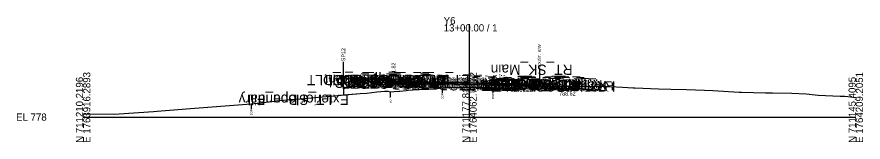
# Model space of a CAD drawing. Extents: x -26 to 1764234, y -10 to 711417.
# Drawn here: x -25.7 to 302.8, y 2990.3 to 3038.9 of the extents above; entities that cross this region are included whole.
import ezdxf

# ---------------------------------------------------------------- set-up
doc = ezdxf.new("R2010")
doc.units = 0
for name, color, linetype in [('Default', 7, 'Continuous'), ('Exist Cross Section Cell', 7, 'Continuous'), ('Exist XS Center Line Elevation Label', 7, 'Continuous'), ('Exist XS Ground Line', 7, 'Continuous'), ('Old_Level_10', 7, 'Continuous'), ('Prop CMT Conc Surface', 7, 'Continuous'), ('Prop CMT Concrete Structures', 7, 'Continuous'), ('Prop CMT Pvmt Course 1', 7, 'Continuous'), ('Prop CMT Pvmt Course 1 CG', 7, 'Continuous'), ('Prop CMT Pvmt Course 2', 7, 'Continuous'), ('Prop CMT Pvmt Course 3', 7, 'Continuous'), ('Prop CMT Pvmt Surface', 7, 'Continuous'), ('Prop CMT Pvmt Surface Shoulder', 7, 'Continuous'), ('Prop CMT Shld Paved Course 1', 7, 'Continuous'), ('Prop CMT Shld Paved Course 2', 7, 'Continuous'), ('Prop CMT Shld Paved Course 3', 7, 'Continuous'), ('Prop CMT Slope Grass', 7, 'Continuous'), ('Prop CMT Subgrade Earthwork', 7, 'Continuous'), ('Prop XS Ditch Standard Text', 7, 'Continuous'), ('Prop XS Earthwork Shape', 7, 'Continuous'), ('Prop XS Hydro Elevations', 7, 'Continuous'), ('Prop XS SE Text', 7, 'Continuous'), ('Prop XS Shear Point Element', 7, 'Continuous'), ('Prop XS Shear Point Label', 7, 'Continuous'), ('Prop XS Side Slope Text', 7, 'Continuous'), ('Scratch_Level_7', 7, 'Continuous')]:
    doc.layers.add(name, color=color, linetype=linetype)

msp = doc.modelspace()

# ---------------------------------------------------------------- linework, layer by layer
at = {"layer": 'Exist Cross Section Cell'}
for p, q in [((150, 3000), (150, 3036.03)), ((0, 3000), (150, 3000)), ((150, 3000), (300, 3000))]:
    msp.add_line(p, q, dxfattribs=at)
at = {"layer": 'Exist XS Ground Line'}
msp.add_lwpolyline([(0, 3001.2), (12.23, 3001.09), (13.95, 3001.22), (27.35, 3002.19), (28.81, 3002.31), (43.31, 3003.44), (45.03, 3003.58), (65.32, 3005.15), (67.55, 3005.41), (73.31, 3006.07), (74.98, 3006.25), (77.82, 3006.58), (80.81, 3006.86), (81.16, 3006.88), (107.6, 3009.21), (110.17, 3009.31), (113.99, 3009.75), (115.55, 3009.92), (117.05, 3010.07), (117.98, 3010.12), (118.32, 3010.02), (119.25, 3009.76), (120.63, 3009.88), (122.53, 3010.07), (122.96, 3010.11), (125.42, 3010.33), (126.25, 3010.39), (127.98, 3010.54), (129.53, 3010.65), (130.54, 3010.73), (133.1, 3010.84), (134.1, 3010.87), (135.66, 3010.92), (136.11, 3010.97), (138.44, 3011.21), (139.81, 3011.38), (140.27, 3011.43), (141.27, 3011.47), (141.67, 3011.48), (143.35, 3011.51), (145.97, 3011.56), (148.47, 3011.56), (149.26, 3011.55), (150, 3011.55), (151.03, 3011.55), (152.55, 3011.56), (153.59, 3011.56), (155.84, 3011.53), (156.35, 3011.53), (156.69, 3011.53), (158.41, 3011.53), (159.14, 3011.52), (159.98, 3011.4), (166.85, 3010.15), (169.51, 3010.62), (174.65, 3011.68), (186.97, 3012), (187.49, 3012), (203.14, 3011.88), (204.58, 3011.85), (209.4, 3011.57), (213.58, 3011.31), (214.24, 3011.3), (223.43, 3010.91), (228.15, 3010.85), (234.24, 3010.68), (241.3, 3010.4), (244.49, 3010.3), (254.73, 3009.71), (255.69, 3009.68), (264.97, 3009.45), (267.61, 3009.37), (275.22, 3009.29), (280.76, 3009.03), (285.46, 3008.49), (293.92, 3008.09), (295.7, 3008.09), (299.08, 3007.74), (300, 3007.65)], dxfattribs=at)
at = {"layer": 'Old_Level_10'}
for p, q in [((177.15, 3019.15), (177.15, 3011.75)), ((119.25, 3009.76), (119.25, 3007.71)), ((139.47, 3011.34), (139.47, 3009.29)), ((159.14, 3011.52), (159.14, 3009.47)), ((65.32, 3005.15), (65.32, 3003.1))]:
    msp.add_line(p, q, dxfattribs=at)
at = {"layer": 'Prop CMT Conc Surface'}
for points in [[(120.53, 3013.82), (120.52, 3014.32), (120.02, 3014.32)], [(122.53, 3013.87), (120.53, 3013.82)]]:
    msp.add_lwpolyline(points, dxfattribs=at)
at = {"layer": 'Prop CMT Concrete Structures'}
for points in [[(122.53, 3013.87), (120.53, 3013.82), (120.52, 3014.32), (120.02, 3014.32)], [(120.02, 3014.32), (120.03, 3013.33), (122.53, 3013.29)], [(122.53, 3013.29), (122.53, 3013.87)]]:
    msp.add_lwpolyline(points, dxfattribs=at)
at = {"layer": 'Prop CMT Pvmt Course 1'}
for points in [[(150, 3013.38), (122.53, 3013.87)], [(122.53, 3013.87), (122.53, 3013.62)], [(122.53, 3013.62), (140.27, 3013.31)], [(140.27, 3013.31), (140.27, 3013.31)], [(140.27, 3013.31), (150, 3013.13)], [(150, 3013.13), (150, 3013.38)], [(150, 3013.38), (174, 3012.96)], [(150, 3013.13), (150, 3013.13), (150, 3013.13)], [(159.14, 3012.97), (150, 3013.13)], [(174, 3012.71), (159.14, 3012.97)], [(159.14, 3012.97), (159.14, 3012.97)], [(174, 3012.96), (174, 3012.71)]]:
    msp.add_lwpolyline(points, dxfattribs=at)
at = {"layer": 'Prop CMT Pvmt Course 1 CG'}
for points in [[(122.53, 3013.29), (119.53, 3013.34), (119.24, 3013.05)], [(119.24, 3013.05), (122.53, 3012.99)], [(122.53, 3012.99), (122.53, 3013.29)]]:
    msp.add_lwpolyline(points, dxfattribs=at)
at = {"layer": 'Prop CMT Pvmt Course 2'}
for points in [[(140.27, 3013.31), (122.53, 3013.62)], [(122.53, 3013.62), (122.53, 3013.37)], [(122.53, 3013.37), (140.27, 3013.06)], [(140.27, 3013.06), (140.27, 3013.31)], [(159.14, 3012.72), (159.14, 3012.97)], [(159.14, 3012.97), (174, 3012.71)], [(174, 3012.46), (159.14, 3012.72)], [(174, 3012.71), (174, 3012.46)]]:
    msp.add_lwpolyline(points, dxfattribs=at)
at = {"layer": 'Prop CMT Pvmt Course 3'}
for points in [[(140.27, 3013.06), (122.53, 3013.37)], [(122.53, 3013.37), (122.53, 3012.99)], [(122.53, 3012.99), (140.27, 3012.68)], [(140.27, 3012.68), (140.27, 3013.06)], [(159.14, 3012.72), (174, 3012.46)], [(159.14, 3012.35), (159.14, 3012.72)], [(174, 3012.09), (159.14, 3012.35)], [(174, 3012.46), (174, 3012.09)]]:
    msp.add_lwpolyline(points, dxfattribs=at)
at = {"layer": 'Prop CMT Pvmt Surface'}
for points in [[(150, 3013.38), (122.53, 3013.87)], [(150, 3013.38), (174, 3012.96)]]:
    msp.add_lwpolyline(points, dxfattribs=at)
at = {"layer": 'Prop CMT Pvmt Surface Shoulder'}
msp.add_lwpolyline([(174, 3012.96), (176, 3012.93)], dxfattribs=at)
at = {"layer": 'Prop CMT Shld Paved Course 1'}
for points in [[(174, 3012.96), (176, 3012.93), (176.25, 3012.67)], [(174, 3012.71), (174, 3012.96)], [(176.25, 3012.67), (174, 3012.71)]]:
    msp.add_lwpolyline(points, dxfattribs=at)
at = {"layer": 'Prop CMT Shld Paved Course 2'}
for points in [[(174, 3012.71), (176.25, 3012.67), (176.51, 3012.42)], [(174, 3012.46), (174, 3012.71)], [(176.51, 3012.42), (174, 3012.46)]]:
    msp.add_lwpolyline(points, dxfattribs=at)
at = {"layer": 'Prop CMT Shld Paved Course 3'}
for points in [[(174, 3012.46), (176.51, 3012.42), (177.01, 3012.41), (177.39, 3012.03)], [(174, 3012.09), (174, 3012.46)], [(177.39, 3012.03), (174, 3012.09)]]:
    msp.add_lwpolyline(points, dxfattribs=at)
at = {"layer": 'Prop CMT Slope Grass'}
msp.add_line((101.1, 3010.93), (101.1, 3008.64), dxfattribs=at)
for points in [[(120.02, 3014.32), (110.52, 3014.51), (101.1, 3010.93)], [(176, 3012.93), (180, 3012.62), (182.89, 3011.89)], [(176, 3012.93), (180, 3012.62), (188, 3010.62), (193.37, 3011.96)]]:
    msp.add_lwpolyline(points, dxfattribs=at)
at = {"layer": 'Prop CMT Subgrade Earthwork'}
for points in [[(122.53, 3012.99), (119.24, 3013.05), (117.92, 3014.37)], [(159.14, 3012.35), (122.53, 3012.99)], [(159.14, 3012.35), (174, 3012.09)], [(174, 3012.09), (177.39, 3012.03)], [(177.39, 3012.03), (182.73, 3011.93)]]:
    msp.add_lwpolyline(points, dxfattribs=at)
at = {"layer": 'Prop XS Earthwork Shape'}
for points in [[(141.27, 3011.47), (141.67, 3011.48), (143.35, 3011.51), (145.97, 3011.56), (148.47, 3011.56), (149.26, 3011.55), (150, 3011.55), (151.03, 3011.55), (152.55, 3011.56), (153.59, 3011.56), (155.84, 3011.53), (156.35, 3011.53), (156.69, 3011.53), (158.41, 3011.53), (159.14, 3011.52), (159.98, 3011.4), (166.85, 3010.15), (169.51, 3010.62), (174.65, 3011.68), (182.89, 3011.89), (182.73, 3011.93), (177.39, 3012.03), (174, 3012.09), (159.14, 3012.35), (122.53, 3012.99), (119.24, 3013.05), (117.92, 3014.37), (110.52, 3014.51), (101.1, 3010.93), (101.1, 3008.64), (107.6, 3009.21), (110.17, 3009.31), (113.99, 3009.75), (115.55, 3009.92), (117.05, 3010.07), (117.98, 3010.12), (118.32, 3010.02), (119.25, 3009.76), (120.63, 3009.88), (122.53, 3010.07), (122.96, 3010.11), (125.42, 3010.33), (126.25, 3010.39), (127.98, 3010.54), (129.53, 3010.65), (130.54, 3010.73), (133.1, 3010.84), (134.1, 3010.87), (135.66, 3010.92), (136.11, 3010.97), (138.44, 3011.21), (139.81, 3011.38), (140.27, 3011.43)], [(186.97, 3012), (187.49, 3012), (193.37, 3011.96), (188, 3010.62), (182.89, 3011.89)]]:
    msp.add_lwpolyline(points, close=True, dxfattribs=at)
at = {"layer": 'Prop XS Shear Point Element'}
msp.add_line((101.1, 3010.93), (101.1, 3021.4), dxfattribs=at)

# ---------------------------------------------------------------- texts
at = {"layer": 'Default'}
msp.add_text('-', height=0.0001, dxfattribs=at).set_placement((0, 3000))
at = {"layer": 'Exist Cross Section Cell'}
for s, p in [('Y6', (140, 3036.03)), ('13+00.00 / 1', (140, 3033.23)), ('EL 778', (-26, 2998.6))]:
    msp.add_text(s, height=2.8, dxfattribs=at).set_placement(p)
for s, p in [('E 1763916.2893', (2.8, 2990)), ('E 1764062.7472', (152.8, 2990)), ('E 1764209.2051', (302.8, 2990)), ('N 711210.2196', (0, 2990)), ('N 711177.8146', (150, 2990)), ('N 711145.4095', (300, 2990))]:
    msp.add_text(s, height=2.8, rotation=90, dxfattribs=at).set_placement(p)
at = {"layer": 'Exist XS Center Line Elevation Label'}
msp.add_text('789.55', height=1, dxfattribs=at).set_placement((147.87, 3009.55))
at = {"layer": 'Old_Level_10'}
for s, height, p in [('EXIST. R/W', 1.181, (177.74, 3019.45)), ('EOP', 0.787, (119.64, 3005.32)), ('EOP', 0.787, (139.87, 3006.89)), ('EOP', 0.787, (159.53, 3007.07)), ('EOP', 0.787, (65.72, 3000.71))]:
    msp.add_text(s, height=height, rotation=90, dxfattribs=at).set_placement(p)
at = {"layer": 'Prop XS Ditch Standard Text'}
msp.add_text('788.62', height=1.5, dxfattribs=at).set_placement((184.86, 3008.37))
at = {"layer": 'Prop XS Hydro Elevations'}
msp.add_text('791.82', height=1.5, rotation=90, dxfattribs=at).set_placement((121.28, 3014.82))
at = {"layer": 'Prop XS SE Text'}
for p in [(133.85, 3014.67), (159.58, 3014.22)]:
    msp.add_text('0.018', height=1.5, rotation=358.9906, dxfattribs=at).set_placement(p)
at = {"layer": 'Prop XS Shear Point Label'}
msp.add_text('SP12', height=1.5, rotation=90, dxfattribs=at).set_placement((101.78, 3021.71))
at = {"layer": 'Prop XS Side Slope Text'}
for s, rotation, p in [('VAR.', 23.2445, (104.01, 3012.48)), ('4:1', 345.9638, (180.47, 3013.27)), ('4:1', 14.0362, (189.99, 3011.94))]:
    msp.add_text(s, height=1.5, rotation=rotation, dxfattribs=at).set_placement(p)
at = {"layer": 'Scratch_Level_7'}
for s, p in [('RT_SK_Main', (190.06, 3020.38)), ('LT_Sub_Trench_Out_DLT', (149.95, 3016.37)), ('LT_CSLP_Pnt', (127.91, 3016.51)), ('LT_CG1_Shelf_Out', (142.26, 3015.34)), ('LT_CG_Top_BOC', (140.93, 3016.32)), ('LT_CG_Bot_BOC', (140.49, 3015.33)), ('LT_CG_Top_Face', (142.35, 3016.32)), ('LT_CG_Top_Gut', (140.4, 3015.82)), ('LT_Sub_OEOP', (137.42, 3015.05)), ('LT_PV1_OEOT', (140.16, 3015.87)), ('LT_PV2_OEOT', (141.17, 3015.62)), ('LT_PV3_OEOT', (141.2, 3015.37)), ('LT_Sub_OEOT', (140.63, 3014.99)), ('LT_CG_Bot_IE', (140.51, 3015.29)), ('LT_PV1_OEEOP', (159.96, 3015.31)), ('LT_PV2_OEEOP', (160.97, 3015.31)), ('LT_PV3_OEEOP', (161, 3015.06)), ('RT_PV1_IEEOP', (169.32, 3015.13)), ('LT_PV1_IEEOP', (168.82, 3015.13)), ('RT_PV2_IEEOP', (170.33, 3015.13)), ('LT_PV2_IEEOP', (169.82, 3015.13)), ('PV1_PGL', (160.68, 3015.38)), ('RT_PV1_OEEOP', (179.34, 3014.97)), ('PV2_PGL', (161.68, 3015.13)), ('RT_PV2_OEEOP', (180.35, 3014.97)), ('RT_PV1_OEOT', (192.14, 3014.96)), ('RT_PS1_OEOP', (194.41, 3014.93)), ('LT_Sub_OEEOP', (160.44, 3014.68)), ('RT_PV3_OEEOP', (180.38, 3014.72)), ('RT_Sub_OEEOP', (179.81, 3014.35)), ('RT_Sub_Trench_Out', (203.34, 3014.03)), ('RT_PS3_Shelf_Out', (201.7, 3014.41)), ('RT_PV2_OEOT', (193.15, 3014.71)), ('RT_PV3_OEOT', (193.18, 3014.46)), ('RT_Sub_OEOT', (192.61, 3014.09)), ('RT_PS2_OEOP', (195.67, 3014.67)), ('RT_PS3_OEOP', (195.95, 3014.42)), ('RT_GS_OS_CTL', (200.12, 3014.62)), ('RT_Sub_OSS_DLT', (206.19, 3013.93)), ('Exterior Boundary', (206.66, 3013.89)), ('RT_Slope_Fill', (200.67, 3013.89)), ('Exterior Boundary', (103.19, 3008.74)), ('LT_Slope_Fill', (96.68, 3008.74))]:
    msp.add_text(s, height=4, rotation=180, dxfattribs=at).set_placement(p)

doc.saveas('drawing.dxf')
